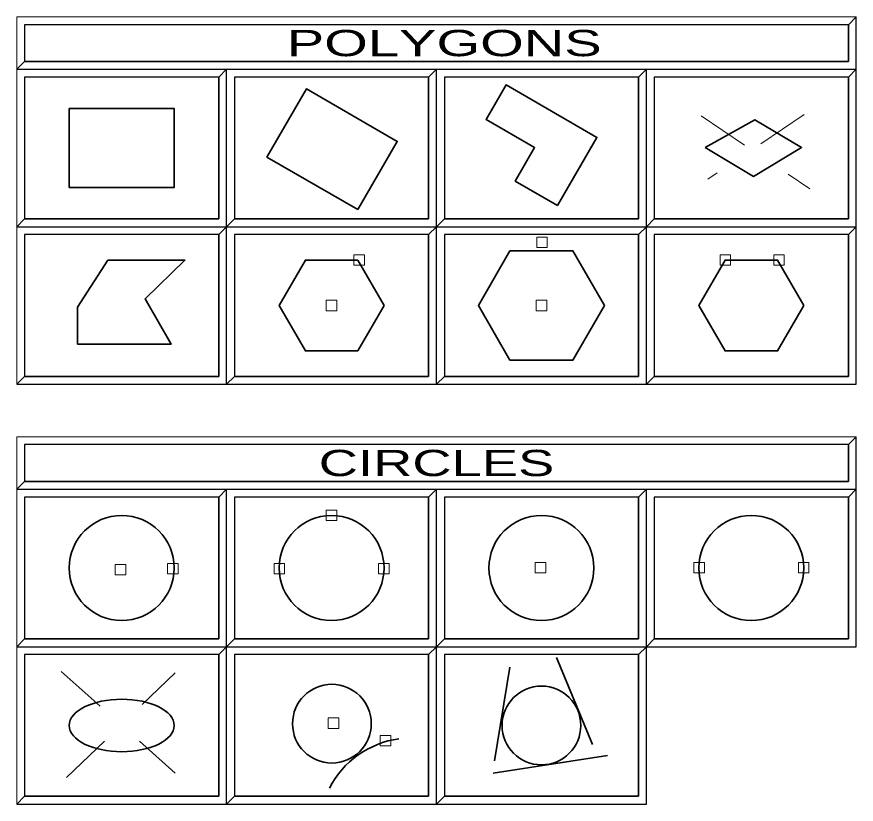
# Model space of a CAD drawing. Extents: x 95906.8 to 95923.6, y 90964.8 to 90972.8.
# Drawn here: x 95910.832 to 95912.432, y 90967.962 to 90969.462 of the extents above; entities that cross this region are included whole.
import ezdxf
from ezdxf.enums import TextEntityAlignment as Align

# ---------------------------------------------------------------- set-up
doc = ezdxf.new("R2010")
doc.units = 0
doc.header["$LTSCALE"] = 0.019
doc.linetypes.add('MEDIUM_DASHED', pattern=[4.5, 3, -1.5])
for name, color, linetype, lineweight in [('11', 7, 'Continuous', 25), ('12', 7, 'Continuous', 25), ('17', 7, 'Continuous', 25), ('2', 7, 'Continuous', 13), ('3', 7, 'Continuous', 25), ('6', 7, 'Continuous', 25), ('7', 7, 'Continuous', 35)]:
    doc.layers.add(name, color=color, linetype=linetype, lineweight=lineweight)

msp = doc.modelspace()

# ---------------------------------------------------------------- linework, layer by layer
at = {"layer": '11'}
for points in [[(95911.2473, 90969.0767), (95911.6173, 90969.0767), (95911.6173, 90969.3467), (95911.2473, 90969.3467)], [(95911.6473, 90969.0767), (95912.0173, 90969.0767), (95912.0173, 90969.3467), (95911.6473, 90969.3467)], [(95912.0473, 90969.0767), (95912.4173, 90969.0767), (95912.4173, 90969.3467), (95912.0473, 90969.3467)], [(95910.8473, 90968.7767), (95911.2173, 90968.7767), (95911.2173, 90969.0467), (95910.8473, 90969.0467)], [(95911.2473, 90968.7767), (95911.6173, 90968.7767), (95911.6173, 90969.0467), (95911.2473, 90969.0467)], [(95911.6473, 90968.7767), (95912.0173, 90968.7767), (95912.0173, 90969.0467), (95911.6473, 90969.0467)], [(95912.0473, 90968.7767), (95912.4173, 90968.7767), (95912.4173, 90969.0467), (95912.0473, 90969.0467)], [(95911.2473, 90968.2767), (95911.6173, 90968.2767), (95911.6173, 90968.5467), (95911.2473, 90968.5467)], [(95911.6473, 90968.2767), (95912.0173, 90968.2767), (95912.0173, 90968.5467), (95911.6473, 90968.5467)], [(95912.0473, 90968.2767), (95912.4173, 90968.2767), (95912.4173, 90968.5467), (95912.0473, 90968.5467)], [(95910.8473, 90967.9767), (95911.2173, 90967.9767), (95911.2173, 90968.2467), (95910.8473, 90968.2467)], [(95911.2473, 90967.9767), (95911.6173, 90967.9767), (95911.6173, 90968.2467), (95911.2473, 90968.2467)], [(95911.6473, 90967.9767), (95912.0173, 90967.9767), (95912.0173, 90968.2467), (95911.6473, 90968.2467)]]:
    msp.add_lwpolyline(points, close=True, dxfattribs=at)
at = {"layer": '12'}
for points in [[(95910.8473, 90969.0767), (95911.2173, 90969.0767), (95911.2173, 90969.3467), (95910.8473, 90969.3467)], [(95910.8473, 90968.2767), (95911.2173, 90968.2767), (95911.2173, 90968.5467), (95910.8473, 90968.5467)]]:
    msp.add_lwpolyline(points, close=True, dxfattribs=at)
at = {"layer": '17'}
for points in [[(95910.8473, 90969.3767), (95912.4173, 90969.3767), (95912.4173, 90969.4467), (95910.8473, 90969.4467)], [(95910.8473, 90968.5767), (95912.4173, 90968.5767), (95912.4173, 90968.6467), (95910.8473, 90968.6467)]]:
    msp.add_lwpolyline(points, close=True, dxfattribs=at)
at = {"layer": '2'}
for points in [[(95910.8323, 90969.4617), (95910.8323, 90969.3617), (95910.8473, 90969.3767), (95910.8473, 90969.4467), (95912.4173, 90969.4467), (95912.4323, 90969.4617)], [(95910.8323, 90969.3617), (95910.8323, 90969.0617), (95910.8473, 90969.0767), (95910.8473, 90969.3467), (95911.2173, 90969.3467), (95911.2323, 90969.3617)], [(95911.2323, 90969.3617), (95911.2323, 90969.0617), (95911.2473, 90969.0767), (95911.2473, 90969.3467), (95911.6173, 90969.3467), (95911.6323, 90969.3617)], [(95911.6323, 90969.3617), (95911.6323, 90969.0617), (95911.6473, 90969.0767), (95911.6473, 90969.3467), (95912.0173, 90969.3467), (95912.0323, 90969.3617)], [(95912.0323, 90969.3617), (95912.0323, 90969.0617), (95912.0473, 90969.0767), (95912.0473, 90969.3467), (95912.4173, 90969.3467), (95912.4323, 90969.3617)], [(95910.8323, 90969.0617), (95910.8323, 90968.7617), (95910.8473, 90968.7767), (95910.8473, 90969.0467), (95911.2173, 90969.0467), (95911.2323, 90969.0617)], [(95911.2323, 90969.0617), (95911.2323, 90968.7617), (95911.2473, 90968.7767), (95911.2473, 90969.0467), (95911.6173, 90969.0467), (95911.6323, 90969.0617)], [(95911.6323, 90969.0617), (95911.6323, 90968.7617), (95911.6473, 90968.7767), (95911.6473, 90969.0467), (95912.0173, 90969.0467), (95912.0323, 90969.0617)], [(95912.0323, 90969.0617), (95912.0323, 90968.7617), (95912.0473, 90968.7767), (95912.0473, 90969.0467), (95912.4173, 90969.0467), (95912.4323, 90969.0617)], [(95910.8323, 90968.6617), (95910.8323, 90968.5617), (95910.8473, 90968.5767), (95910.8473, 90968.6467), (95912.4173, 90968.6467), (95912.4323, 90968.6617)], [(95910.8323, 90968.5617), (95910.8323, 90968.2617), (95910.8473, 90968.2767), (95910.8473, 90968.5467), (95911.2173, 90968.5467), (95911.2323, 90968.5617)], [(95911.2323, 90968.5617), (95911.2323, 90968.2617), (95911.2473, 90968.2767), (95911.2473, 90968.5467), (95911.6173, 90968.5467), (95911.6323, 90968.5617)], [(95911.6323, 90968.5617), (95911.6323, 90968.2617), (95911.6473, 90968.2767), (95911.6473, 90968.5467), (95912.0173, 90968.5467), (95912.0323, 90968.5617)], [(95912.0323, 90968.5617), (95912.0323, 90968.2617), (95912.0473, 90968.2767), (95912.0473, 90968.5467), (95912.4173, 90968.5467), (95912.4323, 90968.5617)], [(95910.8323, 90968.2617), (95910.8323, 90967.9617), (95910.8473, 90967.9767), (95910.8473, 90968.2467), (95911.2173, 90968.2467), (95911.2323, 90968.2617)], [(95911.2323, 90968.2617), (95911.2323, 90967.9617), (95911.2473, 90967.9767), (95911.2473, 90968.2467), (95911.6173, 90968.2467), (95911.6323, 90968.2617)], [(95911.6323, 90968.2617), (95911.6323, 90967.9617), (95911.6473, 90967.9767), (95911.6473, 90968.2467), (95912.0173, 90968.2467), (95912.0323, 90968.2617)]]:
    msp.add_lwpolyline(points, close=True, dxfattribs=at)
at = {"layer": '3'}
for points in [[(95910.8323, 90969.3617), (95912.4323, 90969.3617), (95912.4323, 90969.4617), (95912.4173, 90969.4467), (95912.4173, 90969.3767), (95910.8473, 90969.3767)], [(95910.8323, 90969.0617), (95911.2323, 90969.0617), (95911.2323, 90969.3617), (95911.2173, 90969.3467), (95911.2173, 90969.0767), (95910.8473, 90969.0767)], [(95911.2323, 90969.0617), (95911.6323, 90969.0617), (95911.6323, 90969.3617), (95911.6173, 90969.3467), (95911.6173, 90969.0767), (95911.2473, 90969.0767)], [(95911.6323, 90969.0617), (95912.0323, 90969.0617), (95912.0323, 90969.3617), (95912.0173, 90969.3467), (95912.0173, 90969.0767), (95911.6473, 90969.0767)], [(95912.0323, 90969.0617), (95912.4323, 90969.0617), (95912.4323, 90969.3617), (95912.4173, 90969.3467), (95912.4173, 90969.0767), (95912.0473, 90969.0767)], [(95910.8323, 90968.7617), (95911.2323, 90968.7617), (95911.2323, 90969.0617), (95911.2173, 90969.0467), (95911.2173, 90968.7767), (95910.8473, 90968.7767)], [(95911.2323, 90968.7617), (95911.6323, 90968.7617), (95911.6323, 90969.0617), (95911.6173, 90969.0467), (95911.6173, 90968.7767), (95911.2473, 90968.7767)], [(95911.6323, 90968.7617), (95912.0323, 90968.7617), (95912.0323, 90969.0617), (95912.0173, 90969.0467), (95912.0173, 90968.7767), (95911.6473, 90968.7767)], [(95912.0323, 90968.7617), (95912.4323, 90968.7617), (95912.4323, 90969.0617), (95912.4173, 90969.0467), (95912.4173, 90968.7767), (95912.0473, 90968.7767)], [(95910.8323, 90968.5617), (95912.4323, 90968.5617), (95912.4323, 90968.6617), (95912.4173, 90968.6467), (95912.4173, 90968.5767), (95910.8473, 90968.5767)], [(95910.8323, 90968.2617), (95911.2323, 90968.2617), (95911.2323, 90968.5617), (95911.2173, 90968.5467), (95911.2173, 90968.2767), (95910.8473, 90968.2767)], [(95911.2323, 90968.2617), (95911.6323, 90968.2617), (95911.6323, 90968.5617), (95911.6173, 90968.5467), (95911.6173, 90968.2767), (95911.2473, 90968.2767)], [(95911.6323, 90968.2617), (95912.0323, 90968.2617), (95912.0323, 90968.5617), (95912.0173, 90968.5467), (95912.0173, 90968.2767), (95911.6473, 90968.2767)], [(95912.0323, 90968.2617), (95912.4323, 90968.2617), (95912.4323, 90968.5617), (95912.4173, 90968.5467), (95912.4173, 90968.2767), (95912.0473, 90968.2767)], [(95910.8323, 90967.9617), (95911.2323, 90967.9617), (95911.2323, 90968.2617), (95911.2173, 90968.2467), (95911.2173, 90967.9767), (95910.8473, 90967.9767)], [(95911.2323, 90967.9617), (95911.6323, 90967.9617), (95911.6323, 90968.2617), (95911.6173, 90968.2467), (95911.6173, 90967.9767), (95911.2473, 90967.9767)], [(95911.6323, 90967.9617), (95912.0323, 90967.9617), (95912.0323, 90968.2617), (95912.0173, 90968.2467), (95912.0173, 90967.9767), (95911.6473, 90967.9767)]]:
    msp.add_lwpolyline(points, close=True, dxfattribs=at)
at = {"layer": '6', "linetype": 'MEDIUM_DASHED', "lineweight": 13}
for p, q in [((95912.1366, 90969.2731), (95912.3439, 90969.134)), ((95912.1366, 90969.2731), (95912.3439, 90969.134)), ((95912.3334, 90969.2757), (95912.1497, 90969.1524)), ((95912.3334, 90969.2757), (95912.1497, 90969.1524)), ((95910.9167, 90968.2148), (95911.1344, 90968.0206)), ((95910.9272, 90968.0127), (95911.1344, 90968.2121))]:
    msp.add_line(p, q, dxfattribs=at)
at = {"layer": '6', "lineweight": 35}
for p, q in [((95911.9294, 90968.0757), (95911.8612, 90968.241)), ((95911.7431, 90968.0442), (95911.772, 90968.2226)), ((95911.7405, 90968.0206), (95911.9583, 90968.0547))]:
    msp.add_line(p, q, dxfattribs=at)
for points in [[(95911.8632, 90969.1021), (95911.9382, 90969.232), (95911.765, 90969.332), (95911.7269, 90969.266), (95911.8193, 90969.2127), (95911.7824, 90969.1488)], [(95911.4824, 90969.0944), (95911.3092, 90969.1944), (95911.3842, 90969.3243), (95911.5574, 90969.2243)], [(95910.9323, 90969.1367), (95911.1323, 90969.1367), (95911.1323, 90969.2867), (95910.9323, 90969.2867)], [(95912.1445, 90969.2127), (95912.2389, 90969.2652), (95912.3281, 90969.2127), (95912.2363, 90969.1576)], [(95912.1445, 90969.2127), (95912.2389, 90969.2652), (95912.3281, 90969.2127), (95912.2363, 90969.1576)], [(95911.9525, 90968.9117), (95911.8924, 90969.0158), (95911.7722, 90969.0158), (95911.7121, 90968.9117), (95911.7722, 90968.8076), (95911.8924, 90968.8076)], [(95910.9481, 90968.8378), (95910.9481, 90968.9087), (95911.0059, 90968.9979), (95911.1528, 90968.9979), (95911.0767, 90968.9244), (95911.1265, 90968.8378)], [(95911.5323, 90968.9117), (95911.4823, 90968.9983), (95911.3823, 90968.9983), (95911.3323, 90968.9117), (95911.3823, 90968.8251), (95911.4823, 90968.8251)], [(95912.3323, 90968.9117), (95912.2823, 90968.9983), (95912.1823, 90968.9983), (95912.1323, 90968.9117), (95912.1823, 90968.8251), (95912.2823, 90968.8251)]]:
    msp.add_lwpolyline(points, close=True, dxfattribs=at)
at = {"layer": '6', "lineweight": 13}
for points in [[(95911.8234, 90969.022), (95911.8434, 90969.022), (95911.8434, 90969.042), (95911.8234, 90969.042)], [(95911.4748, 90968.9883), (95911.4948, 90968.9883), (95911.4948, 90969.0083), (95911.4748, 90969.0083)], [(95912.1727, 90968.9883), (95912.1927, 90968.9883), (95912.1927, 90969.0083), (95912.1727, 90969.0083)], [(95912.275, 90968.9883), (95912.295, 90968.9883), (95912.295, 90969.0083), (95912.275, 90969.0083)], [(95911.4223, 90968.9017), (95911.4423, 90968.9017), (95911.4423, 90968.9217), (95911.4223, 90968.9217)], [(95911.8223, 90968.9017), (95911.8423, 90968.9017), (95911.8423, 90968.9217), (95911.8223, 90968.9217)], [(95911.4222, 90968.5019), (95911.4422, 90968.5019), (95911.4422, 90968.5219), (95911.4222, 90968.5219)], [(95911.0201, 90968.3985), (95911.0401, 90968.3985), (95911.0401, 90968.4185), (95911.0201, 90968.4185)], [(95911.1197, 90968.4005), (95911.1397, 90968.4005), (95911.1397, 90968.4205), (95911.1197, 90968.4205)], [(95911.3226, 90968.4005), (95911.3426, 90968.4005), (95911.3426, 90968.4205), (95911.3226, 90968.4205)], [(95911.5218, 90968.4005), (95911.5418, 90968.4005), (95911.5418, 90968.4205), (95911.5218, 90968.4205)], [(95911.8205, 90968.4024), (95911.8405, 90968.4024), (95911.8405, 90968.4224), (95911.8205, 90968.4224)], [(95912.123, 90968.4024), (95912.143, 90968.4024), (95912.143, 90968.4224), (95912.123, 90968.4224)], [(95912.3222, 90968.4024), (95912.3422, 90968.4024), (95912.3422, 90968.4224), (95912.3222, 90968.4224)], [(95911.446, 90968.106), (95911.426, 90968.106), (95911.426, 90968.126), (95911.446, 90968.126)], [(95911.545, 90968.0727), (95911.525, 90968.0727), (95911.525, 90968.0927), (95911.545, 90968.0927)]]:
    msp.add_lwpolyline(points, close=True, dxfattribs=at)
at = {"layer": '6', "lineweight": 35}
for centre, radius in [((95911.0323, 90968.4117), 0.1), ((95911.4323, 90968.4117), 0.1), ((95911.8323, 90968.4117), 0.1), ((95912.2323, 90968.4117), 0.1), ((95911.4329, 90968.1151), 0.075), ((95911.8323, 90968.1117), 0.075)]:
    msp.add_circle(centre, radius, dxfattribs=at)
msp.add_arc((95911.5853, 90967.9113), 0.1768, 98.0074, 152.699, dxfattribs=at)
msp.add_ellipse((95911.0323, 90968.1117), major_axis=(0.1, 0), ratio=0.5, dxfattribs=at)

# ---------------------------------------------------------------- texts
at = {"layer": '7'}
for s, width, p in [('        POLYGONS       ', 1.6, (95911.6322, 90969.3867)), ('        CIRCLES        ', 1.55, (95911.6323, 90968.5867))]:
    msp.add_text(s, height=0.04999, dxfattribs=dict(at, width=width)).set_placement(p, align=Align.CENTER)

doc.saveas('drawing.dxf')
